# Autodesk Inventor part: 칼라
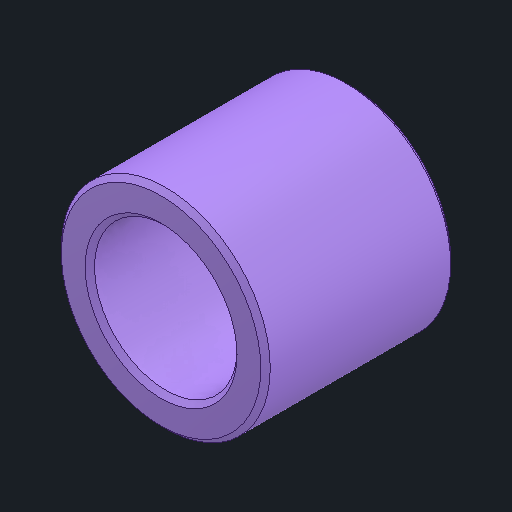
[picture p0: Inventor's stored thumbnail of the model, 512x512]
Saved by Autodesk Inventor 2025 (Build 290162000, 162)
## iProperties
Created: 2025-08
Part Number: 칼라
Material: 스테인리스강
Document SubType Name: Modeling
Designer: infra012
Density: 8.08 g/cm^3
Appearance: 기본값
Author: jhkim
Sending System: Autodesk Inventor 2026
Preprocessor: ST-DEVELOPER v20.1
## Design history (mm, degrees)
sketch "스케치1"
  geometry: 1 further point
  constraints: 1 other
feature "솔리드1"
node "솔리드2"
